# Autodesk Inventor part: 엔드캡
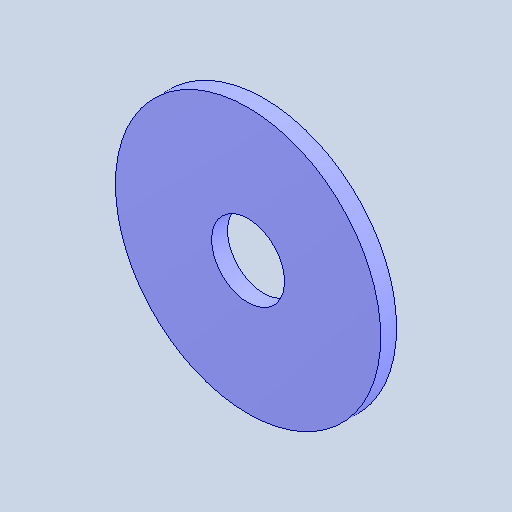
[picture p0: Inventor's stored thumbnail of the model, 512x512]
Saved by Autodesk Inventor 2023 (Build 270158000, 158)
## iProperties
Created: 2024-09
Part Number: 엔드캡
Material: 강철, 연강
Document SubType Name: Modeling
Designer: home
Density: 7.85 g/cm^3
Appearance: 기본값
Author: jhkim
Sending System: Autodesk Inventor 2025
Preprocessor: ST-DEVELOPER v20
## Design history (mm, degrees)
feature "솔리드1"
node "솔리드2"
